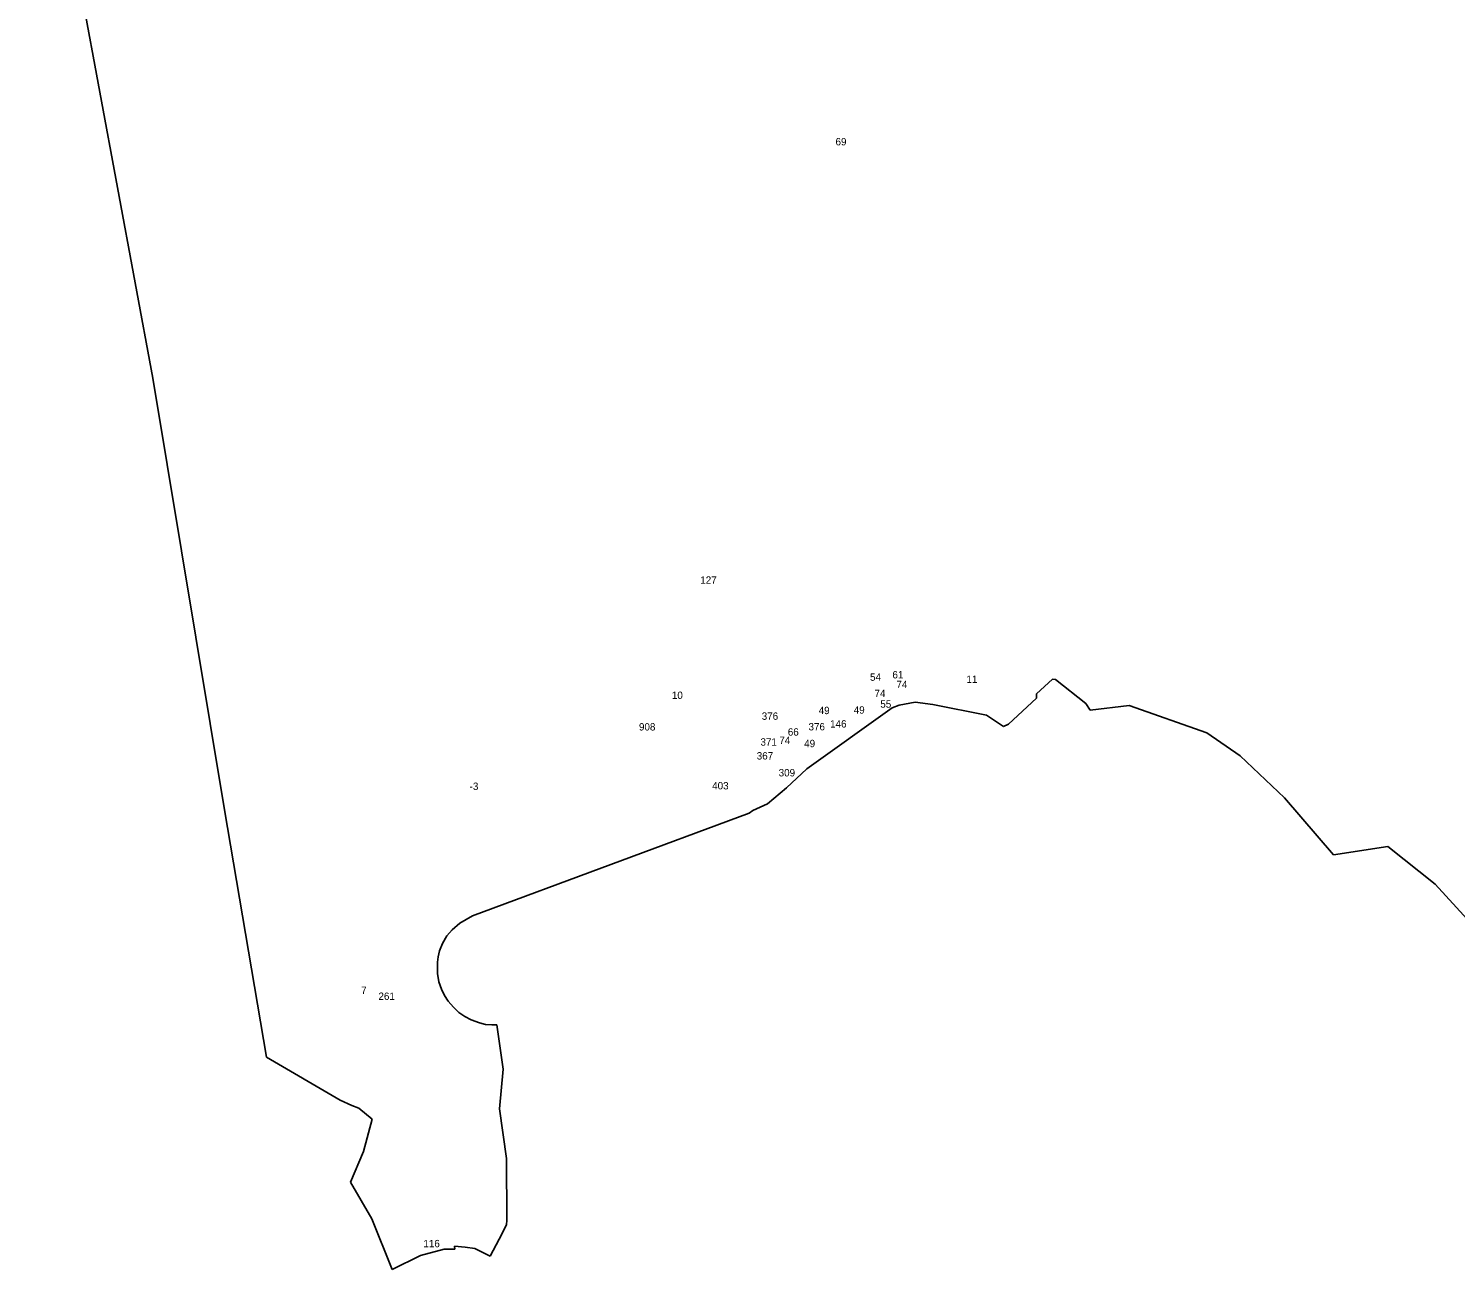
# Model space of a CAD drawing. Extents: x -782977 to -778030, y -975420 to -964838.
# Drawn here: x -782043 to -780704, y -972466 to -971301 of the extents above; entities that cross this region are included whole.
import ezdxf

# ---------------------------------------------------------------- set-up
doc = ezdxf.new("R2010")
doc.units = 0
doc.layers.add('Vrstva 13', color=7, linetype='Continuous')
doc.layers.add('Vrstva 24', color=7, linetype='Continuous')

msp = doc.modelspace()

# ---------------------------------------------------------------- linework, layer by layer
at = {"layer": 'Vrstva 13'}
for p, q in [((-782043.07, -971000.31), (-781926.42, -971628.79)), ((-781926.42, -971628.79), (-781859.12, -972034.17)), ((-781082.01, -971911.58), (-781097.18, -971925.23)), ((-781079.3, -971911.74), (-781082.01, -971911.58)), ((-781050.85, -971934.15), (-781079.3, -971911.74)), ((-781210.95, -971933), (-781225.8, -971935.8)), ((-781194.27, -971935.08), (-781210.95, -971933)), ((-781096.94, -971929.15), (-781123.44, -971953.82)), ((-781097.18, -971925.23), (-781096.94, -971929.15)), ((-781046.62, -971940.62), (-781050.85, -971934.15)), ((-781232.42, -971938.28), (-781312.73, -971995.51)), ((-781225.8, -971935.8), (-781232.42, -971938.28)), ((-781143.87, -971945.08), (-781194.27, -971935.08)), ((-781127.95, -971955.94), (-781143.87, -971945.08)), ((-781010.06, -971936.3), (-781046.62, -971940.62)), ((-780937.03, -971961.85), (-781010.06, -971936.3)), ((-781123.44, -971953.82), (-781127.95, -971955.94)), ((-780905.74, -971983.25), (-780937.03, -971961.85)), ((-780864.23, -972022.94), (-780905.74, -971983.25)), ((-781312.73, -971995.51), (-781331.56, -972013.56)), ((-781331.56, -972013.56), (-781349.44, -972028.57)), ((-781349.44, -972028.57), (-781363.25, -972034.84)), ((-780818.18, -972076.4), (-780864.23, -972022.94)), ((-781859.12, -972034.17), (-781819.78, -972266.35)), ((-781366.84, -972037.08), (-781626.28, -972133.7)), ((-781363.25, -972034.84), (-781366.84, -972037.08)), ((-780767.18, -972068.37), (-780818.18, -972076.4)), ((-780722.73, -972103.79), (-780767.18, -972068.37)), ((-780676.27, -972154.73), (-780722.73, -972103.79)), ((-781626.28, -972133.7), (-781638.37, -972140.38)), ((-781645.47, -972146.73), (-781650.39, -972152.3)), ((-781638.37, -972140.38), (-781645.47, -972146.73)), ((-781654.61, -972159.62), (-781657.21, -972166.57)), ((-781650.39, -972152.3), (-781654.61, -972159.62)), ((-781658.53, -972172.11), (-781659.28, -972177.03)), ((-781657.21, -972166.57), (-781658.53, -972172.11)), ((-781659.28, -972177.03), (-781659.24, -972187.7)), ((-781659.24, -972187.7), (-781657.95, -972195.6)), ((-781657.95, -972195.6), (-781655.63, -972202.39)), ((-781655.63, -972202.39), (-781652.78, -972208.26)), ((-781652.78, -972208.26), (-781649.1, -972213.8)), ((-781649.1, -972213.8), (-781644.35, -972219.34)), ((-781644.35, -972219.34), (-781639.22, -972224.22)), ((-781639.22, -972224.22), (-781633.72, -972228.15)), ((-781633.72, -972228.15), (-781627.52, -972231.29)), ((-781627.52, -972231.29), (-781619.83, -972234.14)), ((-781619.83, -972234.14), (-781614.17, -972235.47)), ((-781614.17, -972235.47), (-781608.38, -972236.01)), ((-781608.38, -972236.01), (-781603.63, -972236.01)), ((-781603.63, -972236.01), (-781597.55, -972277.67)), ((-781819.78, -972266.35), (-781750.52, -972306.76)), ((-781597.55, -972277.67), (-781601.01, -972314.88)), ((-781750.52, -972306.76), (-781739.54, -972311.59)), ((-781739.54, -972311.59), (-781732.99, -972314.13)), ((-781732.99, -972314.13), (-781720.48, -972324.36)), ((-781601.01, -972314.88), (-781594.49, -972361.54)), ((-781720.48, -972324.36), (-781728.74, -972354.9)), ((-781728.74, -972354.9), (-781740.94, -972383.68)), ((-781594.49, -972361.54), (-781594.09, -972419.13)), ((-781740.94, -972383.68), (-781720.8, -972417.95)), ((-781720.8, -972417.95), (-781701.9, -972465.55)), ((-781594.37, -972423.77), (-781601.47, -972437.16)), ((-781594.37, -972423.77), (-781594.09, -972419.13)), ((-781642.87, -972446.55), (-781643.17, -972443.6)), ((-781643.17, -972443.6), (-781633.19, -972444.49)), ((-781601.47, -972437.16), (-781609.92, -972453.04)), ((-781701.9, -972465.55), (-781675.26, -972452.33)), ((-781675.26, -972452.33), (-781652.91, -972446.53)), ((-781652.91, -972446.53), (-781642.87, -972446.55)), ((-781633.19, -972444.49), (-781624.14, -972445.92)), ((-781624.14, -972445.92), (-781609.92, -972453.04))]:
    msp.add_line(p, q, dxfattribs=at)

# ---------------------------------------------------------------- texts
at = {"layer": 'Vrstva 24'}
for s, p in [('69', (-781285.649, -971410.382)), ('127', (-781412.593, -971821.872)), ('54', (-781253.269, -971912.962)), ('61', (-781232.265, -971910.752)), ('11', (-781162.763, -971914.992)), ('74', (-781249.096, -971928.272)), ('74', (-781228.496, -971919.832)), ('10', (-781439.262, -971930.012)), ('55', (-781243.606, -971938.252)), ('376', (-781354.925, -971949.582)), ('49', (-781301.485, -971944.262)), ('49', (-781268.585, -971943.842)), ('908', (-781470.131, -971959.632)), ('66', (-781330.439, -971964.432)), ('376', (-781311.005, -971959.542)), ('146', (-781290.745, -971956.842)), ('371', (-781356.112, -971973.832)), ('74', (-781338.396, -971972.262)), ('49', (-781315.095, -971975.272)), ('367', (-781359.605, -971986.872)), ('309', (-781339.031, -972002.722)), ('-3', (-781629.07, -972015.435)), ('403', (-781401.437, -972014.922)), ('7', (-781730.867, -972206.912)), ('261', (-781714.661, -972212.502)), ('116', (-781672.475, -972444.702))]:
    msp.add_text(s, height=6.912, dxfattribs=at).set_placement(p)

doc.saveas('drawing.dxf')
